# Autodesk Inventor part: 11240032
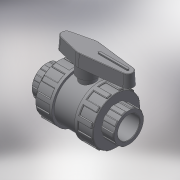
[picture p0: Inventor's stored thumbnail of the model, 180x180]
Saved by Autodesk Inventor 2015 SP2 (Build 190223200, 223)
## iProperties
Created: 2017-11
Part Number: 11240032
Material: Generic
Description: PLASSON BI STOP VALVE CEM PVC 32
Document SubType Name: Modeling
Designer: KIM
Density: 1 g/cm^3
Appearance: Default
Author: KIM
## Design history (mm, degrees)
derived "112400 - 112700.ipt"
feature "Solid1::112400 - 112700.ipt"
tag "TaggingFeature1"
body "Solid1"
other parameters: "d0" = 102, "d1" = 32, "d2" = 66, "d3" = 22, "d4" = 25.6, "d5" = 15.4, "d7" = 44.8, "d8" = 59.4, "d13" = 0.96, "d23" = 22, "d24" = 63.36, "d25" = 0.64, "d26" = 0.96, "d27" = 9.9, "d28" = 4.95, "d29" = 16.5, "d30" = 0, "d35" = 0.96, "d39" = 33, "d45" = 360 deg, "d47" = 0.64, "d50" = 36.3, "d51" = 19.8, "d53" = 0, "d55" = 6.4, "d56" = 3.2, "d57" = 15.4, "d58" = 0, "d59" = 0.96, "d61" = 360 deg, "d63" = 26.4, "d64" = 66, "d66" = 78, "d68" = 13.2, "d69" = 23.4, "d70" = 16.5, "d71" = 3 deg, "d73" = 1.32, "d74" = 31.2, "d75" = 1.98, "d76" = 0, "d77" = 0.64, "d_" = 32, "l_" = 22, "H_" = 102, "K_" = 66, "F_" = 66, "J_" = 78, "d67" = 26.4, "d72" = 6.6
